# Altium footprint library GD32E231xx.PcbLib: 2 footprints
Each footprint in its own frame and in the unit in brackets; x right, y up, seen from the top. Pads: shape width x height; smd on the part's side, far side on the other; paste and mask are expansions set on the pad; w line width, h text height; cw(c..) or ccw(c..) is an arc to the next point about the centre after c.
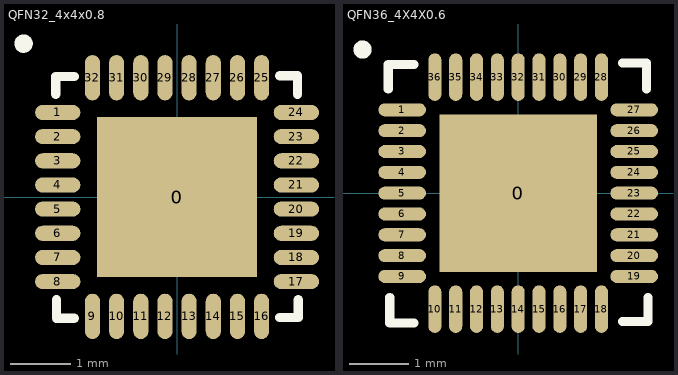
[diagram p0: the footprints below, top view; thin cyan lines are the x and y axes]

## QFN32_4x4x0.8 [mm]
pads (33):
  rect 2.65x2.65 smd: 0(0,0)
  oval 0.75x0.25 smd: 1(-1.975,1.4) 2(-1.975,1) 3(-1.975,0.6) 4(-1.975,0.2) 5(-1.975,-0.2) 6(-1.975,-0.6) 7(-1.975,-1) 8(-1.975,-1.4) 17(1.975,-1.4) 18(1.975,-1) 19(1.975,-0.6) 20(1.975,-0.2) 21(1.975,0.2) 22(1.975,0.6) 23(1.975,1) 24(1.975,1.4)
  oval 0.25x0.75 smd: 9(-1.4,-1.975) 10(-1,-1.975) 11(-0.6,-1.975) 12(-0.2,-1.975) 13(0.2,-1.975) 14(0.6,-1.975) 15(1,-1.975) 16(1.4,-1.975) 25(1.4,1.975) 26(1,1.975) 27(0.6,1.975) 28(0.2,1.975) 29(-0.2,1.975) 30(-0.6,1.975) 31(-1,1.975) 32(-1.4,1.975)
Top Overlay:
  circle w0.152: c-2.54,2.54 r0.076
  lines w0.152: -2.007,1.702 -2.007,1.993 -1.702,1.993 ; -1.993,-1.702 -1.993,-2.007 -1.702,-2.007 ; 1.702,-1.993 2.007,-1.993 2.007,-1.702 ; 1.702,2.007 1.993,2.007 1.993,1.702
3D body "QFN32_4x4x0.8.STEP": height 0.8, standoff 0, extent -2.051,-2.051 2.051,2.051

## QFN36_4X4X0.6 [mm]
pads (37):
  rect 2.65x2.65 smd: 0(0,0)
  oval 0.8x0.22 smd: 1(-1.95,1.4) 2(-1.95,1.05) 3(-1.95,0.7) 4(-1.95,0.35) 5(-1.95,0) 6(-1.95,-0.35) 7(-1.95,-0.7) 8(-1.95,-1.05) 9(-1.95,-1.4) 19(1.95,-1.4) 20(1.95,-1.05) 21(1.95,-0.7) 22(1.95,-0.35) 23(1.95,0) 24(1.95,0.35) 25(1.95,0.7) 26(1.95,1.05) 27(1.95,1.4)
  oval 0.22x0.8 smd: 10(-1.4,-1.95) 11(-1.05,-1.95) 12(-0.7,-1.95) 13(-0.35,-1.95) 14(0,-1.95) 15(0.35,-1.95) 16(0.7,-1.95) 17(1.05,-1.95) 18(1.4,-1.95) 28(1.4,1.95) 29(1.05,1.95) 30(0.7,1.95) 31(0.35,1.95) 32(0,1.95) 33(-0.35,1.95) 34(-0.7,1.95) 35(-1.05,1.95) 36(-1.4,1.95)
Top Overlay:
  circle w0.152: c-2.616,2.413 r0.076
  lines w0.152: -2.184,1.753 -2.184,2.159 -1.753,2.159 ; -2.159,-1.753 -2.159,-2.184 -1.753,-2.184 ; 1.753,-2.159 2.184,-2.159 2.184,-1.753 ; 1.753,2.184 2.159,2.184 2.159,1.753
3D body "QFN36_4X4X0.6.STEP": height 0.6, standoff 0, extent -2.001,-2.001 2.001,2.001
